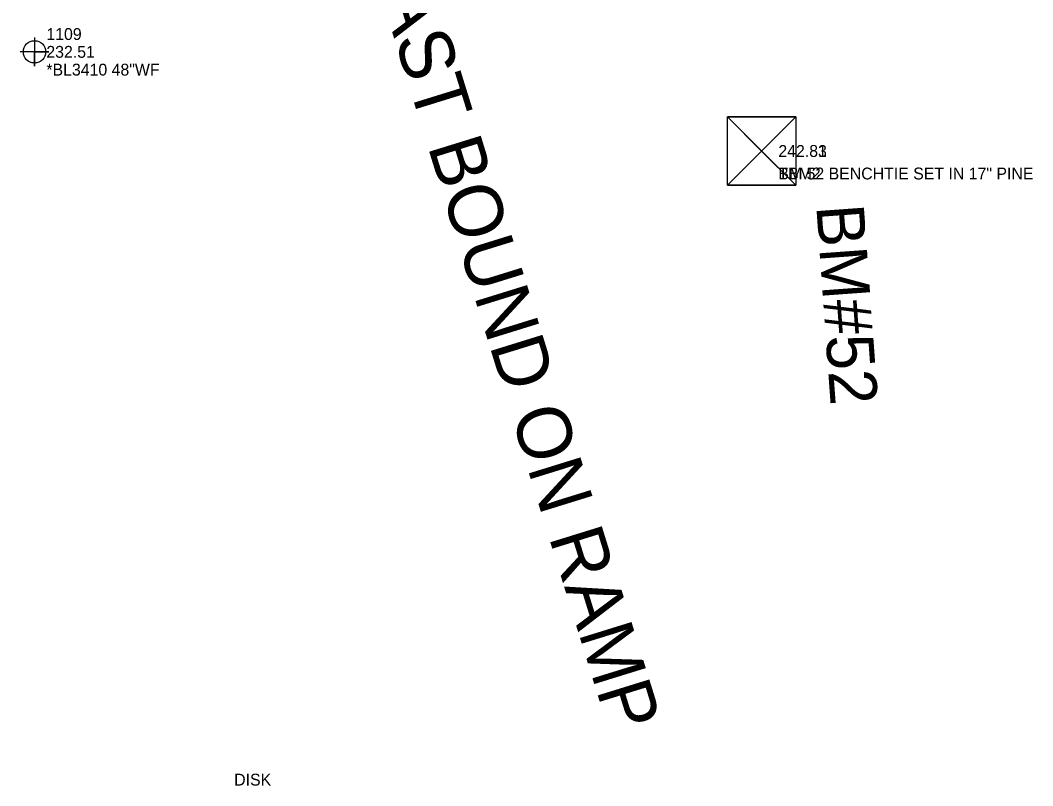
# Model space of a CAD drawing. Extents: x 2130621 to 2131998, y 642516 to 644503.
# Drawn here: x 2131184.9 to 2131398.3, y 642902.8 to 643064.2 of the extents above; entities that cross this region are included whole.
import ezdxf

# ---------------------------------------------------------------- set-up
doc = ezdxf.new("R2010")
doc.units = 0
for name, color, linetype in [('CTL Vertical Benchmark CELL', 7, 'Continuous'), ('CTL Vertical Benchmark Cogo Comment', 7, 'Continuous'), ('CTL Vertical Benchmark Cogo Elevation', 7, 'Continuous'), ('CTL Vertical Benchmark Text', 7, 'Continuous'), ('Exist Other Culture Fence Line Cogo Comment', 7, 'Continuous'), ('Exist Other Culture Fence Line Cogo Elevation', 7, 'Continuous'), ('Exist Other Culture Fence Line Cogo Number', 7, 'Continuous'), ('Exist Other Culture Fence Line Cogo Point CELL', 7, 'Continuous'), ('Exist Right of Way Monument Cogo Comment', 7, 'Continuous'), ('Exist Roads EOT Text', 7, 'Continuous')]:
    doc.layers.add(name, color=color, linetype=linetype)

msp = doc.modelspace()

# ---------------------------------------------------------------- linework, layer by layer
at = {"layer": 'CTL Vertical Benchmark CELL'}
msp.add_line((2131341.16, 643036.63), (2131341.16, 643036.63), dxfattribs=at)
msp.add_lwpolyline([(2131333.96, 643043.81), (2131348.33, 643043.81), (2131348.33, 643029.43), (2131333.96, 643029.43)], close=True, dxfattribs=at)
for points in [[(2131348.33, 643043.81), (2131333.96, 643029.43), (2131341.14, 643036.62), (2131348.33, 643029.43), (2131333.96, 643043.81)], [(2131341.14, 643036.62), (2131348.33, 643043.81), (2131333.96, 643043.81), (2131341.14, 643036.62)], [(2131341.14, 643036.62), (2131333.96, 643029.43), (2131348.33, 643029.43), (2131341.14, 643036.62)]]:
    msp.add_lwpolyline(points, dxfattribs=at)
at = {"layer": 'Exist Other Culture Fence Line Cogo Point CELL'}
msp.add_lwpolyline([(2131187.89, 643060.53), (2131187.89, 643054.53), (2131187.89, 643057.53), (2131190.89, 643057.53), (2131184.89, 643057.53)], dxfattribs=at)
msp.add_circle((2131187.89, 643057.53), 2.34, dxfattribs=at)

# ---------------------------------------------------------------- texts
at = {"layer": 'CTL Vertical Benchmark Cogo Comment'}
for s in ['TBM2', 'BM 52 BENCHTIE SET IN 17" PINE']:
    msp.add_text(s, height=2.5, dxfattribs=at).set_placement((2131344.66, 643030.63))
at = {"layer": 'CTL Vertical Benchmark Cogo Elevation'}
for s in ['242.81', '242.83']:
    msp.add_text(s, height=2.5, dxfattribs=at).set_placement((2131344.66, 643035.38))
at = {"layer": 'CTL Vertical Benchmark Text'}
msp.add_text('BM#52   ', height=10, rotation=274.1431, dxfattribs=at).set_placement((2131352.64, 643025.05))
at = {"layer": 'Exist Other Culture Fence Line Cogo Comment'}
msp.add_text('*BL3410 48"WF', height=2.5, dxfattribs=at).set_placement((2131190.39, 643052.53))
at = {"layer": 'Exist Other Culture Fence Line Cogo Elevation'}
msp.add_text('232.51', height=2.5, dxfattribs=at).set_placement((2131190.39, 643056.28))
at = {"layer": 'Exist Other Culture Fence Line Cogo Number'}
msp.add_text('1109', height=2.5, dxfattribs=at).set_placement((2131190.39, 643060.03))
at = {"layer": 'Exist Right of Way Monument Cogo Comment'}
msp.add_text('DISK', height=2.5, dxfattribs=at).set_placement((2131229.97, 642902.86))
at = {"layer": 'Exist Roads EOT Text'}
msp.add_text('I-40 EAST BOUND ON RAMP', height=11.3735, rotation=287.2196, dxfattribs=at).set_placement((2131248.69, 643108.72))

doc.saveas('drawing.dxf')
